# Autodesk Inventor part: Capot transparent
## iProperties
Author: Flavien MARTY
Shininess: 20.0
PropertySet Name: _Private Model Information
Created: 2001-10
Part Number: Capot transparent
Material: Par défaut
Document SubType Name: Modélisation
Designer: Flavien MARTY
Control State: 0
Master: False
Checked Out: False
PropertySet Name: Design Tracking Control
Density: 0.0
Volumn: 0.0
Area: 0.0
PropertySet Name: Model Information
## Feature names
1. Base1
